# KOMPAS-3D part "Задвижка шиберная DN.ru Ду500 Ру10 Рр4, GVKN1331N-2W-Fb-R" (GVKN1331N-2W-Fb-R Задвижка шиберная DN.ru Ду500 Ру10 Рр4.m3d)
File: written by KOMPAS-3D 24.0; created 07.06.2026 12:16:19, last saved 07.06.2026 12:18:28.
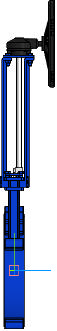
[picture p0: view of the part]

Document properties: Автор: DN.ru; Полное имя файла: E:\Работа\Зайцев\АУТСОРС\Даня\GVKN1331N-2W-Fb-R Задвижка шиберная DN.ru Ду400-600 Ру4-6\исходные материалы\DN500\DN500\GVKN1331N-2W-Fb-R Задвижка шиберная DN.ru Ду500 Ру10 Рр4.m3d

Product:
- Part/product: Задвижка шиберная DN.ru Ду500 Ру10 Рр4  | designation GVKN1331N-2W-Fb-R
    Масса: 192
    Раздел спецификации: Прочие изделия
    Примечание: D040-07324

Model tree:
1. Операция без истории:1

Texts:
  GVKN1331N-2W-Fb-R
